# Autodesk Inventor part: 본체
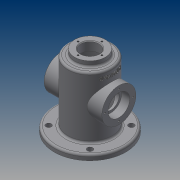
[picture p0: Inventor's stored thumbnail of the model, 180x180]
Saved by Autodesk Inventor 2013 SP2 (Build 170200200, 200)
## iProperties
Created: 2014-12
Part Number: 본체
Material: Generic
Document SubType Name: Modeling
Designer: CADB202
Density: 1 g/cm^3
Author: CADB202
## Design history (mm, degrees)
sketch "스케치1"
  geometry: L1 (0, 51)-(0, -55); L2 (-14.5, 51)-(-22.5, 51); L3 (-22.5, 51)-(-22.5, 46); L4 (-25.5, 43)-(-29.5, 43); L5 (-32.5, 40)-(-32.5, -44); L6 (-35.5, -47)-(-49.5, -47); L7 (-52.5, -50)-(-52.5, -55); L8 (-52.5, -55)-(-27.5, -55); L9 (-13.5, 38)-(-24.5, 38); L10 (-27.5, 35)-(-27.5, -55); L11 (-13.5, 38)-(-13.5, 50); L12 (-14.5, 51)-(-13.5, 50); A1 r 3 centre (-24.5, 35) between (-24.5, 38) and (-27.5, 35); A2 r 3 centre (-25.5, 46) between (-25.5, 43) and (-22.5, 46); A3 r 3 centre (-29.5, 40) between (-29.5, 43) and (-32.5, 40); A4 r 3 centre (-35.5, -44) between (-35.5, -47) and (-32.5, -44); A5 r 3 centre (-49.5, -50) between (-49.5, -47) and (-52.5, -50); 4 further points
  constraints: 24 end point, 10 point on circle, 10 tangent, 6 parallel, 5 centre point, 4 point on line, 3 equal radius, 2 horizontal alignment, 2 perpendicular, 1 midpoint, 1 vertical, 1 vertical alignment
  dimensions: "d0" = 106 distance of L1.start L1.end; "d2" = 55 distance of point (0, 0) L1.end; "d3" = 105 diameter of L7 L1; "d4" = 65 diameter of L5 L1; "d5" = 45 diameter of L3 L1; "d6" = 8 distance of point (-52.5, -47) L7.end; "d7" = 98 distance between parallel lines of L4 L8; "d8" = 55 diameter of L10 L1; "d9" = 5 distance between parallel lines of L9 L4; "d10" = 27 diameter of L11 L1; "d11" = 3 radius of A1; "d12" = 1 distance of L2.start point (-13.5, 51); "d13" = 1 distance of L11.end point (-13.5, 51) (= d12); "d14" = 3 radius of A3
revolve "회전1" sketch "스케치1" stored, may be unused: angle "d15" = 90 deg
node "작업 평면1"
sketch "스케치2"
  geometry: C1 r 25 at (0, 0); 5 further points
  constraints: 1 centre point, 1 coincident, 1 vertical alignment, 5 other
  dimensions: "d17" = 50 diameter of C1; "d18" = 20.5 distance of point (0, 20.5) point (0, 0); "d23" = 360 deg dimension on C1.centre point (0, 20.5) (derived)
extrude "돌출1" join sketch "스케치2" stored distance "d19" = 10; taper "d20" = 0 deg
hole "구멍1" sketch "스케치2" diameter "d25" = 2.459; stored, may be unused: countersink angle "d29" = 90 deg, drill point angle "d31" = 118 deg; dims "d26" = 6, "d27" = 4, "d28" = 2, "d30" = 8
hole "구멍2" diameter "d34" = 25; stored, may be unused: countersink angle "d38" = 90 deg, drill point angle "d40" = 0 deg; dims "d32" = 10, "d33" = 10, "d35" = 6, "d36" = 32, "d37" = 12, "d39" = 8
sketch "스케치3"
  geometry: C1 r 22.5 at (0, 0) reference; 5 further points
  constraints: 1 horizontal alignment, 5 other
  dimensions: "d41" = 17.5 distance of point (17.5, 0) point (0, 0); "d44" = 360 deg dimension on C1.centre point (17.5, 0) (derived)
hole "구멍3" sketch "스케치3" at (17.5, 0), (0, 17.5), (-17.5, 0), (0, -17.5) diameter "d46" = 2.459; stored, may be unused: countersink angle "d50" = 90 deg, drill point angle "d52" = 118 deg; dims "d47" = 6, "d48" = 32, "d49" = 12, "d51" = 8
sketch "스케치4"
  geometry: L1 (0, 0)-(30.406, 30.406); L2 (0, 0)-(43, 0); C1 r 4 at (30.406, 30.406); C2 r 27.5 at (0, 0) reference; C3 r 4 at (-30.406, 30.406); C4 r 4 at (-30.406, -30.406); C5 r 4 at (30.406, -30.406)
  constraints: 4 centre point, 4 end point, 1 coincident, 1 equal length, 1 horizontal, 9 other
  dimensions: "d53" = 43 distance of L1.start L1.end; "d54" = 45 deg angle of L2 L1; "d55" = 8 diameter of C1; "d58" = 360 deg dimension on C2.centre C1.centre (derived)
extrude "돌출2" cut sketch "스케치4" stored distance "d60" = 10; taper "d61" = 0 deg
node "작업 평면2"
sketch "스케치5"
  geometry: L1 (29.5, 45)-(-29.5, 45) reference; 2 further points
  constraints: 1 vertical alignment, 1 other
  dimensions: "d62" = 9 distance from line of L1 point (0, 36)
feature "엠보싱1" sketch "스케치5" dims "d63" = 1, "d64" = 0
node "솔리드1"
mirror "대칭1"
other parameters: "d16" = 42.5
